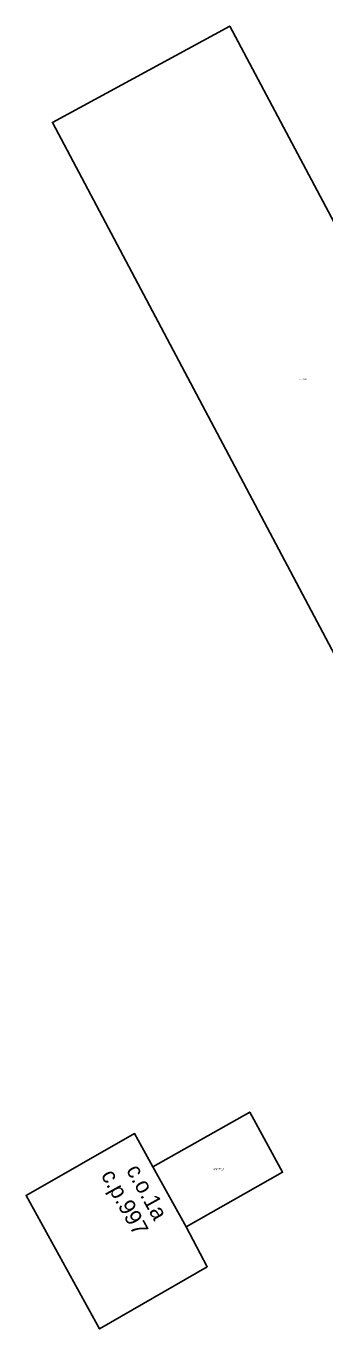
# Model space of a CAD drawing. Extents: x -600391 to -599491, y -1160176 to -1159402.
# Drawn here: x -599738 to -599719.5, y -1159614.7 to -1159534.4 of the extents above; entities that cross this region are included whole.
import ezdxf

# ---------------------------------------------------------------- set-up
doc = ezdxf.new("R2010")
doc.units = 0
for name, color, linetype in [('Level 10', 7, 'Continuous'), ('Level 12', 7, 'Continuous'), ('Level 24', 7, 'Continuous'), ('Level 25', 7, 'Continuous'), ('Level 61', 7, 'Continuous'), ('Level 62', 7, 'Continuous')]:
    doc.layers.add(name, color=color, linetype=linetype)

msp = doc.modelspace()

# ---------------------------------------------------------------- linework, layer by layer
at = {"layer": 'Level 61'}
for points in [[(-599736.35, -1159540.37), (-599725.42, -1159534.43)], [(-599725.42, -1159534.43), (-599705.42, -1159572.04)], [(-599716.41, -1159577.96), (-599736.35, -1159540.37)], [(-599730.16, -1159604.73), (-599724.19, -1159601.36)], [(-599724.19, -1159601.36), (-599722.16, -1159605.06)], [(-599737.98, -1159606.49), (-599731.29, -1159602.68)], [(-599731.29, -1159602.68), (-599730.16, -1159604.73)], [(-599730.16, -1159604.73), (-599728.11, -1159608.43)], [(-599728.11, -1159608.43), (-599730.16, -1159604.73)], [(-599722.16, -1159605.06), (-599728.11, -1159608.43)], [(-599733.45, -1159614.72), (-599737.98, -1159606.49)], [(-599728.11, -1159608.43), (-599726.81, -1159610.89)], [(-599726.81, -1159610.89), (-599733.45, -1159614.72)]]:
    msp.add_lwpolyline(points, dxfattribs=at)
at = {"layer": 'Level 62'}
for points in [[(-599707.78, -1159573.31), (-599716.41, -1159577.96), (-599736.35, -1159540.37), (-599725.42, -1159534.43), (-599705.42, -1159572.04), (-599707.47, -1159573.14), (-599707.78, -1159573.31)], [(-599730.16, -1159604.73), (-599724.19, -1159601.36), (-599722.16, -1159605.06), (-599728.11, -1159608.43), (-599730.16, -1159604.73)], [(-599730.16, -1159604.73), (-599728.11, -1159608.43), (-599726.81, -1159610.89), (-599733.45, -1159614.72), (-599737.98, -1159606.49), (-599731.29, -1159602.68), (-599730.16, -1159604.73)]]:
    msp.add_lwpolyline(points, dxfattribs=at)

# ---------------------------------------------------------------- texts
at = {"layer": 'Level 10'}
msp.add_text('c.o.1a', height=1, rotation=298.98726, dxfattribs=at).set_placement((-599731.833, -1159604.926))
at = {"layer": 'Level 12'}
msp.add_text('c.p.997', height=1, rotation=298.98726, dxfattribs=at).set_placement((-599733.385, -1159605.237))
at = {"layer": 'Level 24'}
msp.add_text('c.z.659', height=0.1, dxfattribs=at).set_placement((-599721.109, -1159556.247))
at = {"layer": 'Level 25'}
msp.add_text('c.pp.997_A', height=0.1, dxfattribs=at).set_placement((-599726.463, -1159604.907))

doc.saveas('drawing.dxf')
